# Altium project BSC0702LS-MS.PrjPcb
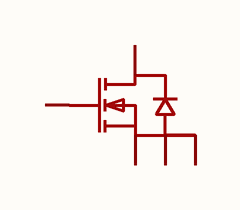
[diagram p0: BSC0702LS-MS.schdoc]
1 sheet, 1 parts. Net scope: global (net labels, ports and power ports of the same name join across sheets).

## Sheet BSC0702LS-MS.schdoc
size 127 x 101 mm

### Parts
Q?  bsc0702ls-ms  [TDSON-8_L5.9-W5.2-P1.27-BL-1]  (value not drawn)

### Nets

Not connected (* = marked no-connect by the designer): Q? 1(S) 2(S) 3(S) 4(G) 5(D)

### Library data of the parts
Q? = bsc0702ls-ms: 数量:1个N沟道;漏源电压(Vdss):60V;连续漏极电流(Id):125A;导通电阻(RDS(on)):2.4mΩ@10V;耗散功率(Pd):113W;阈值电压(Vgs(th)):1.6V;; Manufacturer: MSKSEMI(美森科); AddInBom: yes; ModelId: 6d3ef2b64d5a4f2dbd2ee02e0c7053d2; ModelTransform: 205.511,242.1255,0,0,0,0,0,42.913,0; Number: 1个N沟道; Drain to Source Voltage: 60V; Current - Continuous Drain(Id): 125A; Pd - Power Dissipation: 113W; Gate Threshold Voltage (Vgs(th)): 1.6V; Gate Charge(Qg): 74.37nC; Input Capacitance(Ciss): 4.61nF; Reverse Transfer Capacitance (Crss@Vds): 66pF; Type: N沟道; Output Capacitance(Coss): 2.188nF; Vgs: ±20V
